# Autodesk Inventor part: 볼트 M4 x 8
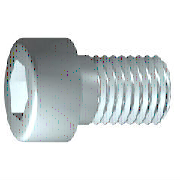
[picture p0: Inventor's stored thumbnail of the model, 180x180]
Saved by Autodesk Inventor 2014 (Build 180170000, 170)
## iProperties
IsCustomPart: 0
Created: 2012-02
Part Number: 볼트 M4 x 8
Material: 스테인리스강
Description: 6각 소켓 머리 캡 나사
Document SubType Name: Modeling
Standard: ISO 4762
Designer: mduedu
Standard Revision: Fourth edition 2004-03-01
Standards Organization: ISO
Language: ko-KR
Size Designation: M4 x 8
Categories: <MemberInstance><Categories><Category DisplayName="조임쇠" InternalName="e4da775c-781d-43d5-af7c-5136215cf5a6" Mnemonic="FSTN"><Category DisplayName="볼트" InternalN
Density: 8.08 g/cm^3
Appearance: 반광택
Mass: 1.89105 g
Surface Area: 2.80587 cm^2
Volume: 0.234041 cm^3
Author: mduedu
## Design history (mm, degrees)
sketch "스케치1"
  geometry: L1 (-1, 0)-(8, 0); L2 (8, 0)-(8, 2); L3 (8, 2)-(1.75, 2); L4 (1.75, 2)-(1.32, 2); L5 (1.32, 2)-(0, 2); L6 (0, 2)-(0, 3.5); L7 (0, 3.5)-(-4, 3.5); L8 (-4, 3.5)-(-4, 1.732); L9 (-4, 1.732)-(-2, 1.732); L10 (-2, 1.732)-(-1, 0); L11 (-6.4, 0)-(10.4, 0) reference; L12 (0, -0.7)-(0, 4.2) reference; L13 (1.75, 2)-(0, 2)
  constraints: 22 end point, 6 parallel, 2 collinear, 2 perpendicular, 1 horizontal, 1 point on line
  dimensions: "d1" = 6.25 distance from line of L3.end L2 (= GEL); "d2" = 0.42952 distance of L4.end L3.end (computed from GAL); "d3" = 4 distance between parallel lines of L8 L6 (= KOH); "d4" = 2 distance of L8.end L9.end (= INTI); "d5" = 60 deg angle of L10 L1; "d6" = 4 diameter of L3 L1 (= GD); "d7" = 4 diameter of L5 L1 (= BDM); "d8" = 3.4641 diameter of L9 L1 (= 1.1547 x SW); "d9" = 7 diameter of L7 L1 (= KOD); "d26" = 8 distance between parallel lines of L12 L2 (= NLG)
revolve "본체" sketch "스케치1" stored, may be unused: angle "d10" = 90 deg
sketch "스케치2"
  geometry: L1 (0, -4.9)-(0, 4.9) reference; L2 (-4.9, 0)-(4.9, 0) reference; L3 (1.732, 0)-(0.866, -1.5); L4 (0.866, -1.5)-(-0.866, -1.5); L5 (-0.866, -1.5)-(-1.732, 0); L6 (-1.732, 0)-(-0.866, 1.5); L7 (-0.866, 1.5)-(0.866, 1.5); L8 (0.866, 1.5)-(1.732, 0); 2 further points
  constraints: 12 end point, 1 coincident, 1 horizontal alignment, 1 point on line, 12 other
extrude "슬롯" join sketch "스케치2" stored distance "d11" = 10; taper "d12" = 0 deg
workplane "Work Plane1"
fillet "Fillet2" dims "d30" = 0.1 (= R)
body "Solid1"
fillet "모깎기1" dims "d17" = 0.4 (= RR)
feature "스레드" dims "d13" = 6.25 (= GEL), "d14" = 0
chamfer "모따기1" distance "d15" = 0.42941 (= -0.5 x SPD + 0.5 x GD); stored, may be unused: second distance "d16" = 0.42941 (= GUL), angle "d27" = 45 deg
other parameters: "GD" = 4 [user parameter; used in 2 equation terms], "NLG" = 8 [user parameter; used in 1 equation term], "GEL" = 6.25 [user parameter; used in 2 equation terms], "KOD" = 7 [user parameter; used in 1 equation term], "KOH" = 4 [user parameter; used in 1 equation term], "INTI" = 2 [user parameter; used in 1 equation term], "GAL" = 0.42941 (= 0.61345 x PTC) [user parameter; used in 1 equation term], "GUL" = 0.42941 (= 0.61345 x PTC) [user parameter; used in 1 equation term], "BDM" = 4 (= NND) [user parameter; used in 1 equation term], "SW" = 3 [user parameter; used in 2 equation terms], "RR" = 0.4 [user parameter; used in 1 equation term], "SPD" = 3.14117 (= NND - 1.2269 x PTC) [user parameter; used in 1 equation term], "d19" = 0, "d28" = 0, "d29" = 0, "R" = 0.1 [user parameter; used in 1 equation term], "TOA" = 30 deg [user parameter], "GD1" = 3.14117 (= THREADDIA - 1.2269 x PTC) [user parameter], "THREADDIA" = 4 [user parameter; used in 1 equation term], "FAWI" = 45 deg [user parameter], "TPU" = 14.28571 (computed from PTC) [user parameter], "PTC" = 0.7 [user parameter; used in 5 equation terms], "NND" = 4 [user parameter; used in 2 equation terms], "E0" = 3.465 (= 1.155 x SW) [user parameter]
